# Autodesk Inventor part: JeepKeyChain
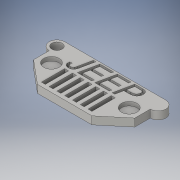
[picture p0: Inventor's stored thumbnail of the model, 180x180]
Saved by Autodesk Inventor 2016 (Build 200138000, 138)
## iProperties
Created: 2015-09
Part Number: JeepKeyChain
Material: Generic
Document SubType Name: Modeling
Designer: PLTW
Density: 1 g/cm^3
Appearance: Default
Author: PLTW
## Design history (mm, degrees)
sketch "Sketch1"
  geometry: L1 (0, 0)-(82.55, 0); L2 (82.55, 0)-(82.55, -12.7); L3 (82.55, -12.7)-(0, -12.7); L4 (0, -12.7)-(0, 0); L5 (82.55, 0)-(0, 0); L6 (0, 0)-(0, 12.7); L7 (0, 12.7)-(82.55, 12.7); L8 (82.55, 12.7)-(82.55, 0); L9 (82.55, 12.7)-(63.5, 28.575); L10 (63.5, 28.575)-(19.05, 28.575); L11 (19.05, 28.575)-(0, 12.7); A1 r 6.35 centre (82.55, -6.35) between (82.55, -12.7) and (82.55, 0); A2 r 6.35 centre (0, -6.35) between (0, 0) and (0, -12.7)
  constraints: 22 end point, 4 parallel, 4 point on circle, 3 horizontal, 2 centre point, 2 midpoint, 2 perpendicular, 1 equal length
  dimensions: "d0" = 12.7 distance of L3.end L1.start; "d1" = 82.55 distance of L2.end L3.end; "d2" = 82.55 distance of L6.end L7.end (= d1); "d3" = 12.7 distance of L5.end L6.end (= d0); "d4" = 15.875 distance between parallel lines of L7 L10; "d5" = 44.45 distance of L9.end L10.end
extrude "Extrusion1" new body sketch "Sketch1" distance "d6" = 6.35; taper "d7" = 0 deg
sketch "Sketch2" dims "d16" = 25.4
  geometry: L1 (-63.5, -25.4)-(-60.325, -25.4); L2 (-60.325, -25.4)-(-60.325, -6.35); L3 (-60.325, -6.35)-(-63.5, -6.35); L4 (-63.5, -6.35)-(-63.5, -25.4); L5 (-63.5, -28.575)-(-19.05, -28.575) reference; L6 (-53.975, -25.4)-(-53.975, -6.35); L7 (-57.15, -6.35)-(-57.15, -25.4); L8 (-53.975, -6.35)-(-57.15, -6.35); L9 (-57.15, -25.4)-(-53.975, -25.4); L10 (-47.625, -25.4)-(-47.625, -6.35); L11 (-50.8, -6.35)-(-50.8, -25.4); L12 (-47.625, -6.35)-(-50.8, -6.35); L13 (-50.8, -25.4)-(-47.625, -25.4); L14 (-41.275, -25.4)-(-41.275, -6.35); L15 (-44.45, -6.35)-(-44.45, -25.4); L16 (-41.275, -6.35)-(-44.45, -6.35); L17 (-44.45, -25.4)-(-41.275, -25.4); L18 (-34.925, -25.4)-(-34.925, -6.35); L19 (-38.1, -6.35)-(-38.1, -25.4); L20 (-34.925, -6.35)-(-38.1, -6.35); L21 (-38.1, -25.4)-(-34.925, -25.4); L22 (-28.575, -25.4)-(-28.575, -6.35); L23 (-31.75, -6.35)-(-31.75, -25.4); L24 (-28.575, -6.35)-(-31.75, -6.35); L25 (-31.75, -25.4)-(-28.575, -25.4); L26 (-22.225, -25.4)-(-22.225, -6.35); L27 (-25.4, -6.35)-(-25.4, -25.4); L28 (-22.225, -6.35)-(-25.4, -6.35); L29 (-25.4, -25.4)-(-22.225, -25.4); 1 further point
  constraints: 56 end point, 2 horizontal, 2 parallel, 1 perpendicular, 1 vertical alignment, 48 other
  dimensions: "d8" = 19.05 distance of L1.end L2.end; "d9" = 3.175 distance of L2.end L3.end; "d10" = 3.175 distance between parallel lines of L5 L1; "d13" = 6.35 distance of L1.end L6.start
extrude "Extrusion2" cut sketch "Sketch2" distance "d18" = 3.175; taper "d19" = 0 deg
sketch "Sketch3"
  geometry: L1 (-82.55, 0)-(-82.55, -12.7) reference; L2 (0, -12.7)-(0, 0) reference; C1 r 6.35 at (-73.025, -7.669); C2 r 6.35 at (-9.525, -7.669)
  constraints: 2 centre point, 1 equal radius, 1 horizontal alignment
  dimensions: "d20" = 12.7 diameter of C1; "d21" = 9.525 distance from line of L1 C1.centre; "d22" = 9.525 distance from line of L2 C2.centre (= d21)
extrude "Extrusion3" cut sketch "Sketch3" distance "d23" = 3.175; taper "d24" = 0 deg
sketch "Sketch4"
  geometry: L1 (-62.094, 10.306)-(-18.767, 10.306); L2 (-18.767, 10.306)-(-18.767, -3.318); L3 (-18.767, -3.318)-(-62.094, -3.318); L4 (-62.094, -3.318)-(-62.094, 10.306); 1 further point
  constraints: 2 other
extrude "Extrusion4" cut sketch "Sketch4" distance "d25" = 3.175; taper "d26" = 0 deg
sketch "Sketch7"
  geometry: C1 r 4.233 at (-82.55, 6.35); A1 r 6.35 centre (-82.55, 6.35) between (-82.55, 12.7) and (-82.55, 0) reference; 1 further point
  constraints: 1 centre point, 1 coincident
  dimensions: "d29" = 8.46667 diameter of C1
extrude "Extrusion5" cut sketch "Sketch7" stored distance "d30" = 1.651; taper "d31" = 0 deg
body "Solid1"
